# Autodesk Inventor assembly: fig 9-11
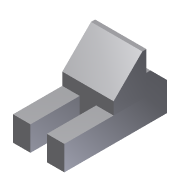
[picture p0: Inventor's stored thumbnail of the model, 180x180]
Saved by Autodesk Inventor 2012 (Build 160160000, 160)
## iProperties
Shininess: 64.0
Length Units: 11269
Angle Units: 11279
Time Units: 11290
Mass Units: 11283
Length Display Precision: 3
Angle Display Precision: 2
Created: 2002-01
Part Number: fig 9-11
Document SubType Name: Assembly
Designer: ***
Density: 0.0
Volumn: 0.0
Area: 0.0
PropertySet Name: Model Information
Control State: 0
Master: False
Checked Out: False
Author: ***
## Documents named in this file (3)
- C:\Users\CadCim\Documents\SAILESH\inventor-2011-fact-prt\c09_inv_2011-prt\c09_inv_2012_prt\fig 9-11.iam
- C:\Users\CadCim\Documents\SAILESH\inventor-2011-fact-prt\c09_inv_2011-prt\c09_inv_2012_prt\Part3.ipt
- C:\Users\CadCim\Documents\SAILESH\inventor-2011-fact-prt\c09_inv_2011-prt\c09_inv_2012_prt\Part4.ipt
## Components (2 placed, 2 different names)
1. Part3:1 — Mate:1
2. Part4:1 — Mate:1
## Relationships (1: Mate 1)
- Mate:1: Part3:1 ↔ Part4:1
